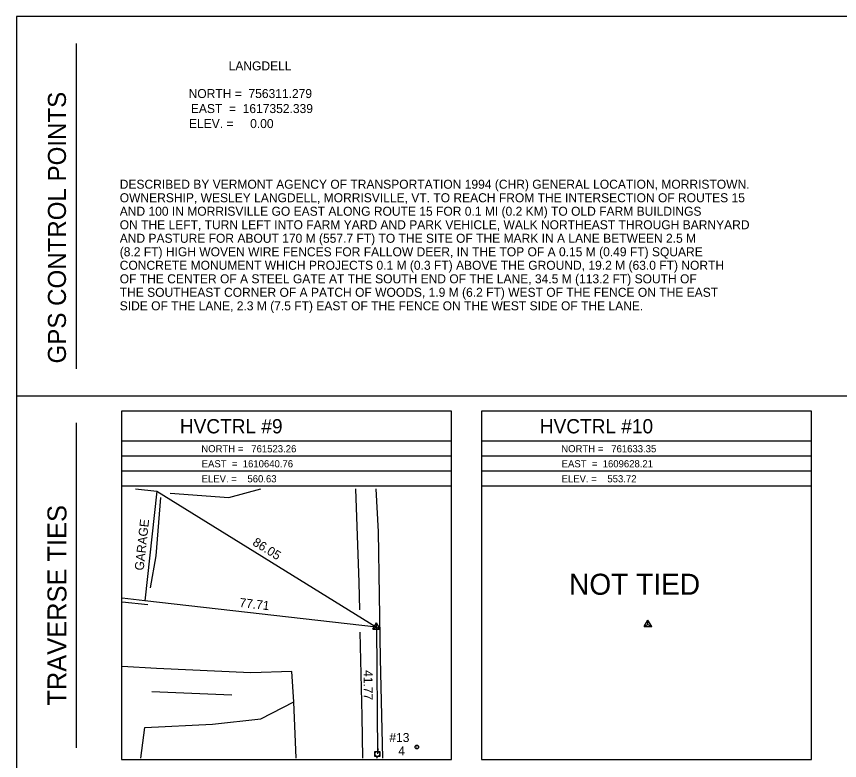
# Model space of a CAD drawing. Extents: x 1609637 to 1610277, y 761117 to 761537.
# Drawn here: x 1609637.2 to 1609911.6, y 761289.4 to 761537.3 of the extents above; entities that cross this region are included whole.
import ezdxf

# ---------------------------------------------------------------- set-up
doc = ezdxf.new("R2010")
doc.units = 0
for name, color, linetype in [('CPSM', 7, 'Continuous'), ('Default', 7, 'Continuous'), ('LAHR', 7, 'Continuous'), ('LBC', 7, 'Continuous'), ('LFNC', 7, 'Continuous'), ('NBL2', 7, 'Continuous'), ('PET', 7, 'Continuous'), ('RDG', 7, 'Continuous'), ('U_C', 7, 'Continuous'), ('UP', 7, 'Continuous'), ('UPGW', 7, 'Continuous')]:
    doc.layers.add(name, color=color, linetype=linetype)

msp = doc.modelspace()

# ---------------------------------------------------------------- linework, layer by layer
at = {"layer": 'CPSM'}
for p, q in [((1609756.02, 761333.16), (1609757.27, 761335.32)), ((1609756.02, 761333.16), (1609757.27, 761333.88)), ((1609758.52, 761333.16), (1609757.27, 761335.32)), ((1609757.27, 761333.88), (1609757.27, 761335.32)), ((1609757.27, 761333.88), (1609757.27, 761333.88)), ((1609757.27, 761333.88), (1609758.52, 761333.16)), ((1609846.5, 761334.07), (1609847.75, 761336.23)), ((1609846.5, 761334.07), (1609847.75, 761334.79)), ((1609846.5, 761334.07), (1609849, 761334.07)), ((1609849, 761334.07), (1609847.75, 761336.23)), ((1609847.75, 761334.79), (1609847.75, 761336.23)), ((1609847.75, 761334.79), (1609847.75, 761334.79)), ((1609847.75, 761334.79), (1609849, 761334.07)), ((1609756.02, 761333.16), (1609758.52, 761333.16))]:
    msp.add_line(p, q, dxfattribs=at)
at = {"layer": 'Default'}
for p, q in [((1609684.08, 761379.13), (1609757.27, 761333.88)), ((1609757.27, 761333.88), (1609680.05, 761342.67)), ((1609757.27, 761333.88), (1609757.54, 761291.62))]:
    msp.add_line(p, q, dxfattribs=at)
at = {"layer": 'LAHR'}
msp.add_lwpolyline([(1609682.35, 761312.43), (1609708.98, 761311.27)], dxfattribs=at)
at = {"layer": 'LBC'}
for points in [[(1609684.08, 761379.13), (1609680.05, 761342.67), (1609672.48, 761343.52)], [(1609676.95, 761379.97), (1609684.08, 761379.13)]]:
    msp.add_lwpolyline(points, dxfattribs=at)
at = {"layer": 'LFNC'}
msp.add_lwpolyline([(1609759.36, 761290.23), (1609758.57, 761323.45), (1609757.96, 761365.57), (1609757.13, 761379.97)], dxfattribs=at)
at = {"layer": 'NBL2'}
for p, q in [((1609657.23, 761419.95), (1609657.23, 761528.29)), ((1609637.23, 761410.95), (1610277.23, 761410.95)), ((1609657.23, 761293.62), (1609657.23, 761401.95)), ((1609782.23, 761395.79), (1609672.23, 761395.79)), ((1609902.23, 761395.79), (1609792.23, 761395.79)), ((1609782.23, 761390.79), (1609672.23, 761390.79)), ((1609902.23, 761390.79), (1609792.23, 761390.79)), ((1609782.23, 761385.79), (1609672.23, 761385.79)), ((1609902.23, 761385.79), (1609792.23, 761385.79)), ((1609782.23, 761380.79), (1609672.23, 761380.79)), ((1609902.23, 761380.79), (1609792.23, 761380.79))]:
    msp.add_line(p, q, dxfattribs=at)
for points in [[(1609637.23, 761117.29), (1610277.23, 761117.29), (1610277.23, 761537.29), (1609637.23, 761537.29)], [(1609672.23, 761289.79), (1609782.23, 761289.79), (1609782.23, 761405.79), (1609672.23, 761405.79)], [(1609792.23, 761289.79), (1609902.23, 761289.79), (1609902.23, 761405.79), (1609792.23, 761405.79)]]:
    msp.add_lwpolyline(points, close=True, dxfattribs=at)
at = {"layer": 'PET'}
for points in [[(1609750.3, 761379.97), (1609751.39, 761348.76), (1609751.58, 761339.63)], [(1609751.74, 761332.19), (1609752.33, 761304.16), (1609752.62, 761290.23)], [(1609730.46, 761290.23), (1609729.68, 761309)]]:
    msp.add_lwpolyline(points, dxfattribs=at)
at = {"layer": 'RDG'}
for points in [[(1609688.45, 761378.47), (1609708.05, 761377.07), (1609718.66, 761379.97)], [(1609681.96, 761346.97), (1609683.78, 761357.59), (1609685.33, 761377)], [(1609672.48, 761342.32), (1609681, 761341.39)], [(1609678.73, 761290.23), (1609680.08, 761300.38), (1609702.63, 761301.57), (1609718.65, 761303.32), (1609729.68, 761309), (1609729.02, 761319.11), (1609715.33, 761318.59), (1609683.95, 761320.06), (1609672.48, 761320.77)]]:
    msp.add_lwpolyline(points, dxfattribs=at)
at = {"layer": 'UP'}
for p, q in [((1609757.79, 761293.29), (1609757.54, 761292.45)), ((1609756.71, 761290.79), (1609756.71, 761292.45)), ((1609756.71, 761292.45), (1609758.38, 761292.45)), ((1609758.38, 761290.79), (1609756.71, 761290.79)), ((1609757.38, 761290.23), (1609757.54, 761290.79)), ((1609757.54, 761291.62), (1609757.54, 761291.62)), ((1609758.38, 761292.45), (1609758.38, 761290.79))]:
    msp.add_line(p, q, dxfattribs=at)
msp.add_circle((1609757.54, 761291.62), 0.833, dxfattribs=at)
at = {"layer": 'UPGW'}
for radius in [0.625, 0.0833]:
    msp.add_circle((1609770.69, 761293.93), radius, dxfattribs=at)

# ---------------------------------------------------------------- texts
at = {"layer": 'Default'}
for s, height, p in [('DESCRIBED BY VERMONT AGENCY OF TRANSPORTATION 1994 (CHR) GENERAL LOCATION, MORRISTOWN. ', 3, (1609671.66, 761479.9)), ('OWNERSHIP, WESLEY LANGDELL, MORRISVILLE, VT. TO REACH FROM THE INTERSECTION OF ROUTES 15 ', 3, (1609671.66, 761475.4)), ('AND 100 IN MORRISVILLE GO EAST ALONG ROUTE 15 FOR 0.1 MI (0.2 KM) TO OLD FARM BUILDINGS ', 3, (1609671.66, 761470.9)), ('ON THE LEFT, TURN LEFT INTO FARM YARD AND PARK VEHICLE, WALK NORTHEAST THROUGH BARNYARD ', 3, (1609671.66, 761466.4)), ('AND PASTURE FOR ABOUT 170 M (557.7 FT) TO THE SITE OF THE MARK IN A LANE BETWEEN 2.5 M ', 3, (1609671.66, 761461.9)), ('(8.2 FT) HIGH WOVEN WIRE FENCES FOR FALLOW DEER, IN THE TOP OF A 0.15 M (0.49 FT) SQUARE ', 3, (1609671.66, 761457.4)), ('CONCRETE MONUMENT WHICH PROJECTS 0.1 M (0.3 FT) ABOVE THE GROUND, 19.2 M (63.0 FT) NORTH ', 3, (1609671.66, 761452.9)), ('OF THE CENTER OF A STEEL GATE AT THE SOUTH END OF THE LANE, 34.5 M (113.2 FT) SOUTH OF ', 3, (1609671.66, 761448.4)), ('THE SOUTHEAST CORNER OF A PATCH OF WOODS, 1.9 M (6.2 FT) WEST OF THE FENCE ON THE EAST ', 3, (1609671.66, 761443.9)), ('SIDE OF THE LANE, 2.3 M (7.5 FT) EAST OF THE FENCE ON THE WEST SIDE OF THE LANE. ', 3, (1609671.66, 761439.4)), ('NOT TIED', 7, (1609821.46, 761344.65))]:
    msp.add_text(s, height=height, dxfattribs=at).set_placement(p)
for s, rotation, p in [('GARAGE', 83.6961, (1609679.59, 761352.6)), ('86.05', 328.2671, (1609715.69, 761361.35)), ('77.71', 353.5009, (1609711.44, 761340.61)), ('41.77', 270.3741, (1609752.97, 761319.55))]:
    msp.add_text(s, height=3, rotation=rotation, dxfattribs=at).set_placement(p)
at = {"layer": 'NBL2'}
for s, height, p in [('  LANGDELL  ', 3, (1609705.74, 761519.32)), ('NORTH =  756311.279 ', 3, (1609694.63, 761510.11)), ('EAST  =  1617352.339', 3, (1609695.37, 761505.11)), ('ELEV. =     0.00    ', 3, (1609694.74, 761500.11)), ('     HVCTRL #9     ', 4.75, (1609682.88, 761398.41)), ('     HVCTRL #10    ', 4.75, (1609802.88, 761398.41)), ('NORTH =   761523.26 ', 2.375, (1609698.85, 761392.1)), ('NORTH =   761633.35 ', 2.375, (1609818.85, 761392.1)), ('EAST  =  1610640.76 ', 2.375, (1609698.99, 761387.1)), ('EAST  =  1609628.21 ', 2.375, (1609818.99, 761387.1)), ('ELEV. =    560.63   ', 2.375, (1609698.96, 761382.1)), ('ELEV. =    553.72   ', 2.375, (1609818.96, 761382.1))]:
    msp.add_text(s, height=height, dxfattribs=at).set_placement(p)
for s, height, p in [('GPS CONTROL POINTS', 6, (1609653.73, 761421.7)), ('TRAVERSE TIES', 6.3332, (1609653.9, 761307.72))]:
    msp.add_text(s, height=height, rotation=90, dxfattribs=at).set_placement(p)
at = {"layer": 'U_C'}
for s, p in [('#13', (1609761.55, 761295.59)), ('4', (1609764.53, 761291.15))]:
    msp.add_text(s, height=3, dxfattribs=at).set_placement(p)

doc.saveas('drawing.dxf')
